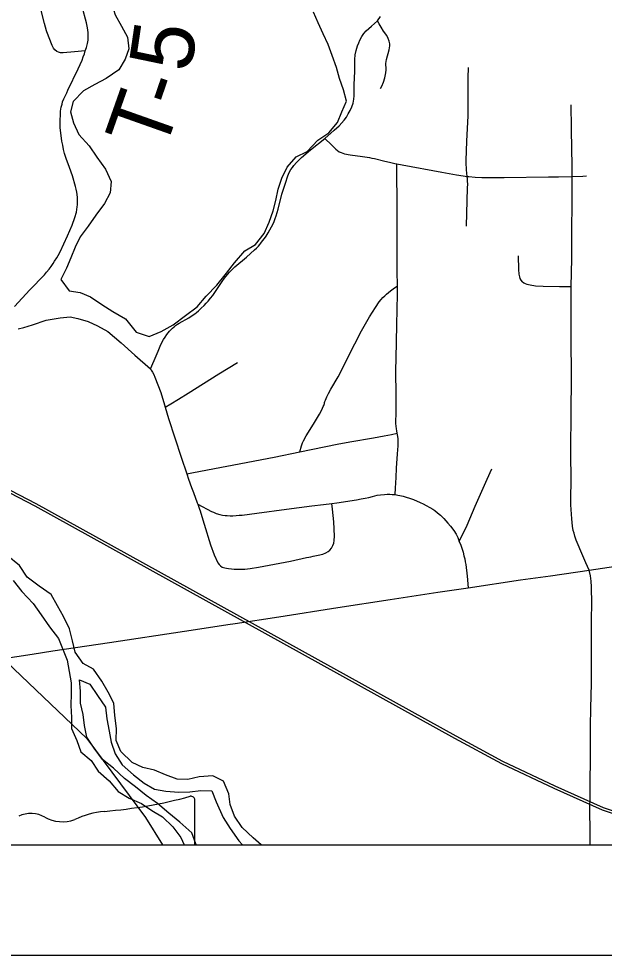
# Model space of a CAD drawing. Extents: x 0 to 34, y 0 to 22.
# Drawn here: x 4.018 to 4.548, y 14 to 14.848 of the extents above; entities that cross this region are included whole.
import ezdxf

# ---------------------------------------------------------------- set-up
doc = ezdxf.new("R2010")
doc.units = 0
for name, color, linetype in [('Default', 7, 'Continuous'), ('GM_X_Corporation', 7, 'Continuous'), ('GM_X_Major_Lake', 7, 'Continuous'), ('GM_X_Minor_River', 7, 'Continuous'), ('GM_X_Rail_Line', 7, 'Continuous'), ('GM_X_State_Route', 7, 'Continuous'), ('GM_X_Township_Road', 7, 'Continuous'), ('GM_X_Township_Road_Text', 7, 'Continuous'), ('SH_Data', 7, 'Continuous')]:
    doc.layers.add(name, color=color, linetype=linetype)

msp = doc.modelspace()

# ---------------------------------------------------------------- linework, layer by layer
at = {"layer": 'Default'}
msp.add_lwpolyline([(3.8475, 14.13222), (3.8475, 14.1), (4.17708, 14.1), (4.17708, 14.14083)], dxfattribs=at)
for centre, major_axis, start_param, end_param in [((4.05968, 14.40852), (0.34952, 0), 4.814394, 5.042369), ((4.17343, 14.14108), (0.00367, 0), 6.197627, 7.989034), ((4.0284, 14.11058), (0.02221, 0), 0.950623, 2.079405), ((4.05707, 14.14231), (0.02672, 0), 4.08156, 5.145723), ((4.10426, 14.07457), (0.07032, 0), 1.699012, 2.107814)]:
    msp.add_ellipse(centre, major_axis=major_axis, ratio=0.8, start_param=start_param, end_param=end_param, dxfattribs=at)
at = {"layer": 'GM_X_Corporation'}
msp.add_lwpolyline([(4.71799, 17.49624), (3.7119, 17.4934), (3.58006, 17.49243), (3.4708, 17.4915), (3.04564, 17.48944), (2.63524, 17.49292), (2.58119, 17.49248), (2.14492, 17.48819), (2.1, 17.48755), (2.1, 14.1), (5.03982, 14.1)], dxfattribs=at)
at = {"layer": 'GM_X_Major_Lake'}
for points in [[(4.06038, 14.94695), (4.0703, 14.93716), (4.07493, 14.92582), (4.08069, 14.91449), (4.0857, 14.90353), (4.08994, 14.89295), (4.0923, 14.88159), (4.09844, 14.87139), (4.10192, 14.86156), (4.10502, 14.85172), (4.11078, 14.84153), (4.11616, 14.83171), (4.11737, 14.8211), (4.11404, 14.81159), (4.10844, 14.80207), (4.09677, 14.79401), (4.08659, 14.78862), (4.07641, 14.78285), (4.06703, 14.7733), (4.06445, 14.7638), (4.06718, 14.75396), (4.07218, 14.74338), (4.08134, 14.73321), (4.08823, 14.72302)], [(4.08823, 14.72302), (4.09627, 14.71209), (4.10127, 14.70075), (4.1006, 14.6905), (4.09537, 14.68098), (4.0875, 14.6703), (4.08039, 14.66038), (4.07327, 14.65084), (4.06881, 14.64133), (4.06472, 14.63181), (4.061, 14.6223), (4.05579, 14.61202), (4.06343, 14.60184), (4.07329, 14.6004), (4.08278, 14.5963), (4.09305, 14.58956), (4.10294, 14.58319), (4.11435, 14.57645), (4.1239, 14.56439), (4.13567, 14.56031), (4.14661, 14.56494), (4.15754, 14.5711), (4.16882, 14.57953), (4.17936, 14.5872), (4.18761, 14.59712), (4.197, 14.60706), (4.206, 14.61775), (4.21312, 14.62729), (4.2225, 14.63798), (4.23229, 14.64375), (4.24017, 14.65367), (4.24463, 14.66394), (4.24833, 14.67421), (4.25053, 14.68371), (4.25272, 14.69397), (4.25605, 14.70386), (4.26089, 14.71376), (4.26915, 14.7233), (4.27895, 14.72793), (4.28871, 14.73825), (4.2985, 14.74477), (4.30638, 14.75431), (4.31047, 14.76383), (4.31455, 14.77372), (4.31182, 14.78394), (4.30834, 14.79415), (4.30561, 14.80399), (4.30174, 14.81496), (4.29788, 14.82479), (4.29364, 14.83462), (4.28903, 14.84444), (4.28479, 14.85427)]]:
    msp.add_lwpolyline(points, dxfattribs=at)
at = {"layer": 'GM_X_Minor_River'}
for points in [[(4.17094, 14.15931), (4.1611, 14.15961), (4.15047, 14.16332), (4.1406, 14.1678), (4.12998, 14.16999), (4.12048, 14.17446), (4.11018, 14.18462), (4.10595, 14.19445), (4.10624, 14.20545), (4.10463, 14.2172), (4.10379, 14.22819), (4.09879, 14.23839), (4.09304, 14.24821), (4.08539, 14.25915), (4.07588, 14.26438), (4.06861, 14.27456), (4.06626, 14.28479), (4.06353, 14.29577), (4.05814, 14.30672), (4.05277, 14.31654), (4.04702, 14.32674), (4.03598, 14.33424), (4.02532, 14.3425), (4.01843, 14.35306), (4.007, 14.36207)], [(4.01247, 14.33936), (4.0205, 14.32956), (4.0308, 14.31864), (4.03807, 14.30846), (4.04535, 14.29752), (4.05376, 14.28696), (4.06148, 14.2673), (4.06345, 14.25708), (4.06504, 14.24685), (4.06512, 14.23699), (4.06482, 14.22637), (4.06529, 14.21537), (4.06536, 14.20551), (4.07037, 14.19455), (4.07385, 14.18434), (4.08338, 14.17645), (4.08951, 14.16663), (4.09942, 14.15799), (4.10782, 14.1482), (4.1177, 14.1422), (4.12872, 14.13736), (4.13823, 14.13099), (4.14774, 14.12537), (4.15727, 14.11634), (4.16453, 14.10654), (4.16742, 14.1)], [(4.07586, 14.21811), (4.07351, 14.22833), (4.07343, 14.23933), (4.07259, 14.24956), (4.08209, 14.24547), (4.08898, 14.23528), (4.09625, 14.22472), (4.09747, 14.21411), (4.09944, 14.20312), (4.10142, 14.1929), (4.1049, 14.18231), (4.11141, 14.1725), (4.1217, 14.16347), (4.13122, 14.15596), (4.14073, 14.15035), (4.15096, 14.14853), (4.1627, 14.14787), (4.17254, 14.14795), (4.18275, 14.14916), (4.19259, 14.14886), (4.19646, 14.13903), (4.203, 14.12467), (4.20913, 14.11486), (4.21717, 14.10354), (4.22038, 14.1)], [(4.17832, 14.1), (4.1782, 14.10096), (4.17434, 14.11079), (4.16367, 14.12057), (4.15376, 14.12883), (4.14348, 14.13748), (4.1332, 14.1446), (4.1233, 14.15249), (4.1134, 14.15999), (4.10349, 14.1694), (4.09359, 14.17729), (4.08594, 14.18747), (4.07943, 14.19766), (4.07707, 14.20826), (4.07586, 14.21811)], [(4.2372, 14.1), (4.23002, 14.1063), (4.2201, 14.1157), (4.21321, 14.12589), (4.20934, 14.13648), (4.20813, 14.14633), (4.20312, 14.15767), (4.19362, 14.16252), (4.18114, 14.16167), (4.17094, 14.15931)]]:
    msp.add_lwpolyline(points, dxfattribs=at)
at = {"layer": 'GM_X_Rail_Line'}
for points in [[(4.59399, 14.11583), (4.5467, 14.13137), (4.50292, 14.15115), (4.4554, 14.17333), (4.41289, 14.19637), (4.03238, 14.40668), (3.56218, 14.65114), (3.16185, 14.86779), (3.02758, 14.94055)], [(4.59474, 14.11804), (4.54755, 14.13355), (4.5039, 14.15327), (4.45646, 14.17541), (4.41402, 14.19842), (4.03349, 14.40874), (3.56328, 14.6532), (3.16297, 14.86984), (3.0287, 14.9426)], [(3.0723, 14.82989), (3.09009, 14.80759), (3.10587, 14.79222), (3.15966, 14.77236), (3.21627, 14.75802), (3.24255, 14.75709), (3.27018, 14.75131), (3.2929, 14.73934), (3.33693, 14.70988), (3.43283, 14.67996), (3.53363, 14.65553), (3.58392, 14.63017), (3.64919, 14.57907), (3.73367, 14.50841), (3.81194, 14.43989), (3.86761, 14.39787), (4.07922, 14.19645), (4.13242, 14.12472), (4.14803, 14.1)]]:
    msp.add_lwpolyline(points, dxfattribs=at)
at = {"layer": 'GM_X_State_Route'}
msp.add_line((4.20701, 14.29952), (4.21386, 14.30056), dxfattribs=at)
for points in [[(4.35407, 14.32216), (4.39753, 14.32875), (4.42502, 14.33288), (4.47242, 14.34), (4.49946, 14.3438), (4.53458, 14.34883), (4.59117, 14.35716)], [(4.21386, 14.30056), (4.25331, 14.30646), (4.30665, 14.31496), (4.35407, 14.32216)], [(4.04857, 14.2756), (4.09986, 14.2834), (4.16771, 14.29354)], [(4.16771, 14.29354), (4.17769, 14.29504), (4.20701, 14.29952)], [(3.92447, 14.25672), (4.02983, 14.27275), (4.04857, 14.2756)]]:
    msp.add_lwpolyline(points, dxfattribs=at)
at = {"layer": 'GM_X_Township_Road'}
for points in [[(4.04278, 14.83738), (4.04081, 14.84407), (4.03712, 14.85946)], [(4.06215, 14.78353), (4.07134, 14.80301), (4.07496, 14.81086), (4.07608, 14.81372), (4.0772, 14.81656), (4.07794, 14.81917), (4.07898, 14.82233), (4.07978, 14.82571), (4.08038, 14.82899), (4.08054, 14.83204), (4.08054, 14.83567), (4.08006, 14.83988), (4.079, 14.84464), (4.07496, 14.85894)], [(4.1371, 14.5311), (4.14039, 14.53884), (4.14387, 14.54709), (4.14646, 14.55327), (4.1488, 14.55764), (4.15025, 14.55987), (4.15186, 14.56234), (4.15298, 14.56376), (4.15418, 14.56528), (4.15543, 14.56658), (4.15683, 14.56801), (4.15833, 14.56926), (4.15977, 14.57046), (4.16139, 14.57154), (4.16294, 14.57257), (4.17163, 14.57741), (4.17486, 14.57949), (4.1773, 14.58107), (4.17874, 14.58223), (4.18062, 14.58374), (4.18295, 14.58596), (4.1855, 14.5884), (4.18747, 14.59054), (4.18925, 14.59245), (4.19129, 14.59503), (4.19343, 14.59773), (4.19459, 14.59948), (4.19643, 14.60223), (4.20122, 14.60941), (4.20328, 14.61214), (4.20536, 14.61491), (4.20698, 14.61679), (4.20862, 14.61871), (4.21099, 14.62103), (4.21353, 14.62352), (4.22391, 14.63245), (4.23134, 14.63896), (4.23296, 14.64059), (4.23475, 14.64238), (4.23599, 14.64378), (4.23715, 14.64509), (4.23858, 14.64695), (4.24037, 14.64927), (4.24176, 14.65135), (4.24375, 14.65436), (4.24525, 14.65703), (4.24674, 14.6597), (4.24805, 14.66252), (4.24906, 14.6647), (4.25009, 14.66746), (4.25098, 14.66984), (4.25193, 14.67287), (4.2528, 14.67566), (4.25615, 14.68939), (4.25927, 14.69944), (4.26145, 14.70594), (4.26273, 14.70887), (4.26431, 14.71162), (4.26573, 14.71361), (4.26688, 14.71522), (4.26936, 14.71811), (4.27387, 14.72248), (4.2819, 14.72942), (4.29488, 14.73987), (4.30344, 14.7472), (4.30796, 14.75137), (4.31252, 14.75632), (4.31465, 14.75925), (4.3163, 14.76206), (4.31805, 14.76506), (4.31956, 14.76835), (4.32069, 14.77177), (4.32142, 14.77531), (4.32163, 14.77829), (4.32158, 14.78282), (4.32171, 14.78829), (4.32229, 14.80065), (4.32234, 14.80371), (4.32223, 14.8112), (4.32257, 14.81562), (4.32327, 14.81937), (4.32458, 14.82362), (4.32578, 14.82652), (4.32677, 14.82889), (4.32854, 14.83226), (4.33035, 14.83491), (4.33246, 14.83734), (4.33482, 14.83952), (4.33722, 14.84157), (4.34269, 14.84636), (4.34547, 14.85039)], [(4.34544, 14.78522), (4.34659, 14.78727), (4.34811, 14.7908), (4.34936, 14.79484), (4.35035, 14.79926), (4.35064, 14.80205), (4.35057, 14.8044), (4.35025, 14.80601), (4.3502, 14.80777), (4.35078, 14.81148), (4.3532, 14.8201), (4.3538, 14.82375), (4.35378, 14.82559), (4.35334, 14.82801), (4.35252, 14.83033), (4.35105, 14.83306), (4.34831, 14.83708), (4.34595, 14.8407), (4.34412, 14.84367), (4.34269, 14.84636)], [(4.07794, 14.81917), (4.06803, 14.81825), (4.05784, 14.81737), (4.05539, 14.81747), (4.05361, 14.81786), (4.05201, 14.81856), (4.05042, 14.81995), (4.04913, 14.82175), (4.04794, 14.82393), (4.04307, 14.83642), (4.04278, 14.83738)], [(4.42326, 14.6604), (4.42432, 14.69497), (4.42451, 14.69832), (4.42439, 14.70125), (4.42424, 14.70338), (4.42409, 14.70548), (4.42382, 14.70834), (4.42351, 14.71146), (4.42331, 14.71384), (4.42316, 14.71566), (4.423, 14.71804), (4.42307, 14.71994), (4.42383, 14.73728), (4.42479, 14.76018), (4.42499, 14.78003), (4.42499, 14.79479), (4.4251, 14.80413)], [(4.01374, 14.58761), (4.02763, 14.60257), (4.0408, 14.61643), (4.04284, 14.61884), (4.04516, 14.62158), (4.04695, 14.62398), (4.04881, 14.62649), (4.05011, 14.62854), (4.05208, 14.63166), (4.05333, 14.63396), (4.055, 14.63706), (4.06189, 14.65162), (4.06597, 14.66132), (4.06849, 14.66827), (4.0698, 14.67299), (4.07028, 14.67556), (4.07068, 14.67778), (4.07082, 14.67975), (4.07098, 14.682), (4.0709, 14.684), (4.0708, 14.68624), (4.07044, 14.68894), (4.07016, 14.69106), (4.06952, 14.69402), (4.069, 14.69643), (4.06624, 14.70596), (4.0636, 14.71356), (4.06046, 14.7218), (4.05904, 14.7263), (4.05814, 14.72993), (4.05745, 14.73375), (4.05678, 14.7375), (4.05524, 14.74982), (4.05503, 14.75415), (4.05517, 14.75706), (4.05534, 14.76055), (4.05553, 14.76446), (4.05615, 14.76814), (4.05682, 14.77075), (4.0574, 14.77299), (4.05836, 14.77557), (4.05956, 14.7781), (4.06106, 14.78123), (4.06215, 14.78353)], [(4.53458, 14.34883), (4.53169, 14.35544), (4.52703, 14.36594), (4.52452, 14.37169), (4.52289, 14.37593), (4.52161, 14.37951), (4.52083, 14.3822), (4.52019, 14.38481), (4.51949, 14.38853), (4.51889, 14.39519), (4.51808, 14.40801), (4.51801, 14.41668), (4.51814, 14.42724), (4.5181, 14.45765), (4.51822, 14.49114), (4.51863, 14.52336), (4.51837, 14.55997), (4.5183, 14.60159), (4.51838, 14.60568), (4.51887, 14.63066), (4.51897, 14.65622), (4.51915, 14.68146), (4.51907, 14.7054), (4.51905, 14.71643), (4.51878, 14.72956), (4.51853, 14.74925), (4.51815, 14.77014)], [(4.29488, 14.73987), (4.30108, 14.734), (4.30287, 14.73211), (4.30494, 14.73011), (4.30637, 14.72893), (4.30803, 14.72776), (4.3098, 14.72698), (4.31287, 14.72604), (4.31784, 14.72513), (4.32929, 14.72346), (4.33337, 14.72289), (4.33551, 14.72256), (4.33753, 14.72207), (4.3399, 14.72154), (4.34949, 14.71936), (4.35368, 14.71834), (4.35962, 14.71695), (4.36027, 14.71683), (4.36508, 14.71593), (4.40106, 14.7094), (4.41441, 14.70683), (4.42052, 14.70593), (4.42409, 14.70548), (4.42545, 14.70531), (4.43138, 14.70481), (4.43726, 14.70449), (4.4416, 14.70449), (4.45741, 14.70443), (4.49768, 14.70503), (4.50688, 14.70511), (4.51907, 14.7054), (4.52877, 14.70574), (4.53217, 14.70603)], [(4.3586, 14.4172), (4.35898, 14.42296), (4.35962, 14.43272), (4.3601, 14.44128), (4.36079, 14.45408), (4.36116, 14.45791), (4.3614, 14.46154), (4.36153, 14.46496), (4.36137, 14.4679), (4.36103, 14.47001), (4.36076, 14.47136), (4.36046, 14.47285), (4.36013, 14.47489), (4.35982, 14.47679), (4.35955, 14.47926), (4.35947, 14.48165), (4.35937, 14.48468), (4.35963, 14.48943), (4.35954, 14.50663), (4.35941, 14.52994), (4.35969, 14.54063), (4.36036, 14.57104), (4.36079, 14.5988), (4.36072, 14.60621), (4.36058, 14.61976), (4.36042, 14.64011), (4.36046, 14.65185), (4.36065, 14.67979), (4.36033, 14.71072), (4.36027, 14.71683)], [(4.47407, 14.60994), (4.47305, 14.61133), (4.47215, 14.61301), (4.47159, 14.61438), (4.47112, 14.61679), (4.47082, 14.62111), (4.47065, 14.63336)], [(4.47407, 14.60994), (4.47534, 14.60904), (4.47654, 14.60844), (4.47808, 14.60795), (4.48108, 14.60716), (4.48595, 14.60641), (4.49275, 14.6059), (4.50762, 14.60574), (4.5135, 14.60571), (4.51838, 14.60568)], [(4.27233, 14.45608), (4.27392, 14.46137), (4.27422, 14.46237), (4.27476, 14.46399), (4.2756, 14.46583), (4.27809, 14.47052), (4.28474, 14.48114), (4.29025, 14.49021), (4.29227, 14.49406), (4.29295, 14.49553), (4.29364, 14.49702), (4.29397, 14.49789), (4.29429, 14.49875), (4.2946, 14.49983), (4.29483, 14.50065), (4.29513, 14.50171), (4.29557, 14.5027), (4.29619, 14.50415), (4.29691, 14.50569), (4.29845, 14.50877), (4.30059, 14.51263), (4.30713, 14.52401), (4.32208, 14.5539), (4.32813, 14.56549), (4.33553, 14.57834), (4.34083, 14.58671), (4.3444, 14.5917), (4.34618, 14.59393), (4.34772, 14.59577), (4.34927, 14.59737), (4.35094, 14.5989), (4.35271, 14.60039), (4.35467, 14.60191), (4.35704, 14.6036), (4.36072, 14.60621)], [(4.01705, 14.56731), (4.02236, 14.56862), (4.02996, 14.57107), (4.04259, 14.57521), (4.05513, 14.57728), (4.06426, 14.57819), (4.07126, 14.57682), (4.08054, 14.57393), (4.08891, 14.57012), (4.09834, 14.56493), (4.11035, 14.55474), (4.12268, 14.54362), (4.1371, 14.5311), (4.13774, 14.53005), (4.13888, 14.52816), (4.13991, 14.52595), (4.14101, 14.52358), (4.14641, 14.5097), (4.14959, 14.49848), (4.15017, 14.49657), (4.1534, 14.48605), (4.16475, 14.45129), (4.16988, 14.436), (4.17146, 14.4313), (4.17416, 14.4237), (4.17595, 14.41908), (4.17929, 14.40993), (4.17986, 14.40845), (4.18048, 14.40686), (4.18151, 14.40419), (4.18204, 14.40257), (4.18271, 14.40051), (4.18562, 14.39048), (4.19127, 14.37171), (4.19469, 14.36262), (4.1981, 14.35546)], [(4.15017, 14.49657), (4.15529, 14.49954), (4.16225, 14.50357), (4.17119, 14.50913), (4.19907, 14.52673), (4.216, 14.537)], [(4.16988, 14.436), (4.17591, 14.43718), (4.20627, 14.44312), (4.24898, 14.45116), (4.27233, 14.45608), (4.30614, 14.46288), (4.31771, 14.46509), (4.33912, 14.46863), (4.34876, 14.4704), (4.3553, 14.47177), (4.36046, 14.47285)], [(4.41676, 14.37486), (4.424, 14.3897), (4.43134, 14.40674), (4.44222, 14.43113), (4.44626, 14.44044)], [(4.17986, 14.40845), (4.19229, 14.40209), (4.1941, 14.40122), (4.19641, 14.40027), (4.1999, 14.39923), (4.20239, 14.39872), (4.20454, 14.39839), (4.20661, 14.39823), (4.20935, 14.39814), (4.21175, 14.39814), (4.21453, 14.39828), (4.21746, 14.3985), (4.22014, 14.3987), (4.23331, 14.40037), (4.26019, 14.40391), (4.28324, 14.40714), (4.29381, 14.40838), (4.30131, 14.40929), (4.30577, 14.40994), (4.32358, 14.41263), (4.32788, 14.41335), (4.33156, 14.414), (4.33493, 14.41474), (4.33816, 14.41566), (4.34032, 14.41623), (4.34229, 14.41671), (4.34546, 14.41714), (4.34897, 14.41747), (4.3515, 14.41755), (4.35384, 14.41758), (4.35603, 14.41746), (4.3586, 14.4172), (4.36103, 14.41683), (4.36289, 14.41645), (4.36587, 14.41572), (4.36881, 14.41482), (4.37173, 14.41389), (4.37525, 14.41274), (4.38149, 14.41018), (4.38398, 14.40895), (4.38699, 14.40746), (4.39018, 14.40555), (4.39278, 14.40401), (4.39469, 14.4027), (4.39723, 14.40078), (4.39991, 14.39855), (4.4028, 14.39565), (4.40473, 14.39357), (4.40661, 14.39142), (4.40894, 14.38876), (4.41192, 14.38471), (4.41391, 14.38139), (4.4154, 14.37832), (4.41676, 14.37486), (4.41813, 14.37144), (4.41921, 14.36862), (4.42028, 14.36514), (4.42111, 14.36182), (4.42177, 14.35917), (4.42234, 14.35635), (4.42272, 14.3539), (4.42394, 14.34348), (4.42502, 14.33288)], [(4.1981, 14.35546), (4.19916, 14.35392), (4.20034, 14.35267), (4.20189, 14.35165), (4.20429, 14.35087), (4.20583, 14.35053), (4.20771, 14.35019), (4.21028, 14.34993), (4.21294, 14.34976), (4.21563, 14.34972), (4.21834, 14.34967), (4.22254, 14.34984), (4.22741, 14.35036), (4.23477, 14.35146), (4.24938, 14.35431), (4.26402, 14.3571), (4.27849, 14.36022), (4.28039, 14.36063), (4.28218, 14.36101), (4.28438, 14.36142), (4.28889, 14.36226), (4.29307, 14.36341), (4.29594, 14.36458), (4.29807, 14.36584), (4.29952, 14.367), (4.30114, 14.36886), (4.30233, 14.37101), (4.30312, 14.37334), (4.30357, 14.37578), (4.30375, 14.37951), (4.30304, 14.3925), (4.30184, 14.40414), (4.30131, 14.40929)], [(4.53548, 14.1), (4.5355, 14.10267), (4.53533, 14.12003), (4.53531, 14.12375), (4.5353, 14.12996), (4.53537, 14.14672), (4.53568, 14.18773), (4.53585, 14.1989), (4.5359, 14.2076), (4.53604, 14.22377), (4.53655, 14.24612), (4.53669, 14.2691), (4.53663, 14.2809), (4.53679, 14.30451), (4.53693, 14.31818), (4.53666, 14.33368), (4.53633, 14.33896), (4.53563, 14.34381), (4.53458, 14.34883)]]:
    msp.add_lwpolyline(points, dxfattribs=at)
at = {"layer": 'SH_Data'}
for p, q in [((2.1, 14.1), (8.9, 14.1)), ((2, 14), (9, 14))]:
    msp.add_line(p, q, dxfattribs=at)

# ---------------------------------------------------------------- texts
at = {"layer": 'GM_X_Township_Road_Text'}
for s, rotation, p in [('5', 81.55944, (4.17337, 14.79866)), ('-', 71.08094, (4.16313, 14.76559)), ('T', 70.51337, (4.14875, 14.72495))]:
    msp.add_text(s, height=0.05682, rotation=rotation, dxfattribs=at).set_placement(p)

doc.saveas('drawing.dxf')
